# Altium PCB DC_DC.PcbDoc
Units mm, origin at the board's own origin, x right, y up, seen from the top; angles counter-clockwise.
Board outline 97.66 x 51.56 mm, 2 copper layers (Top Layer, Bottom Layer); 23 components, 9 nets, 55 pads, 2 vias.
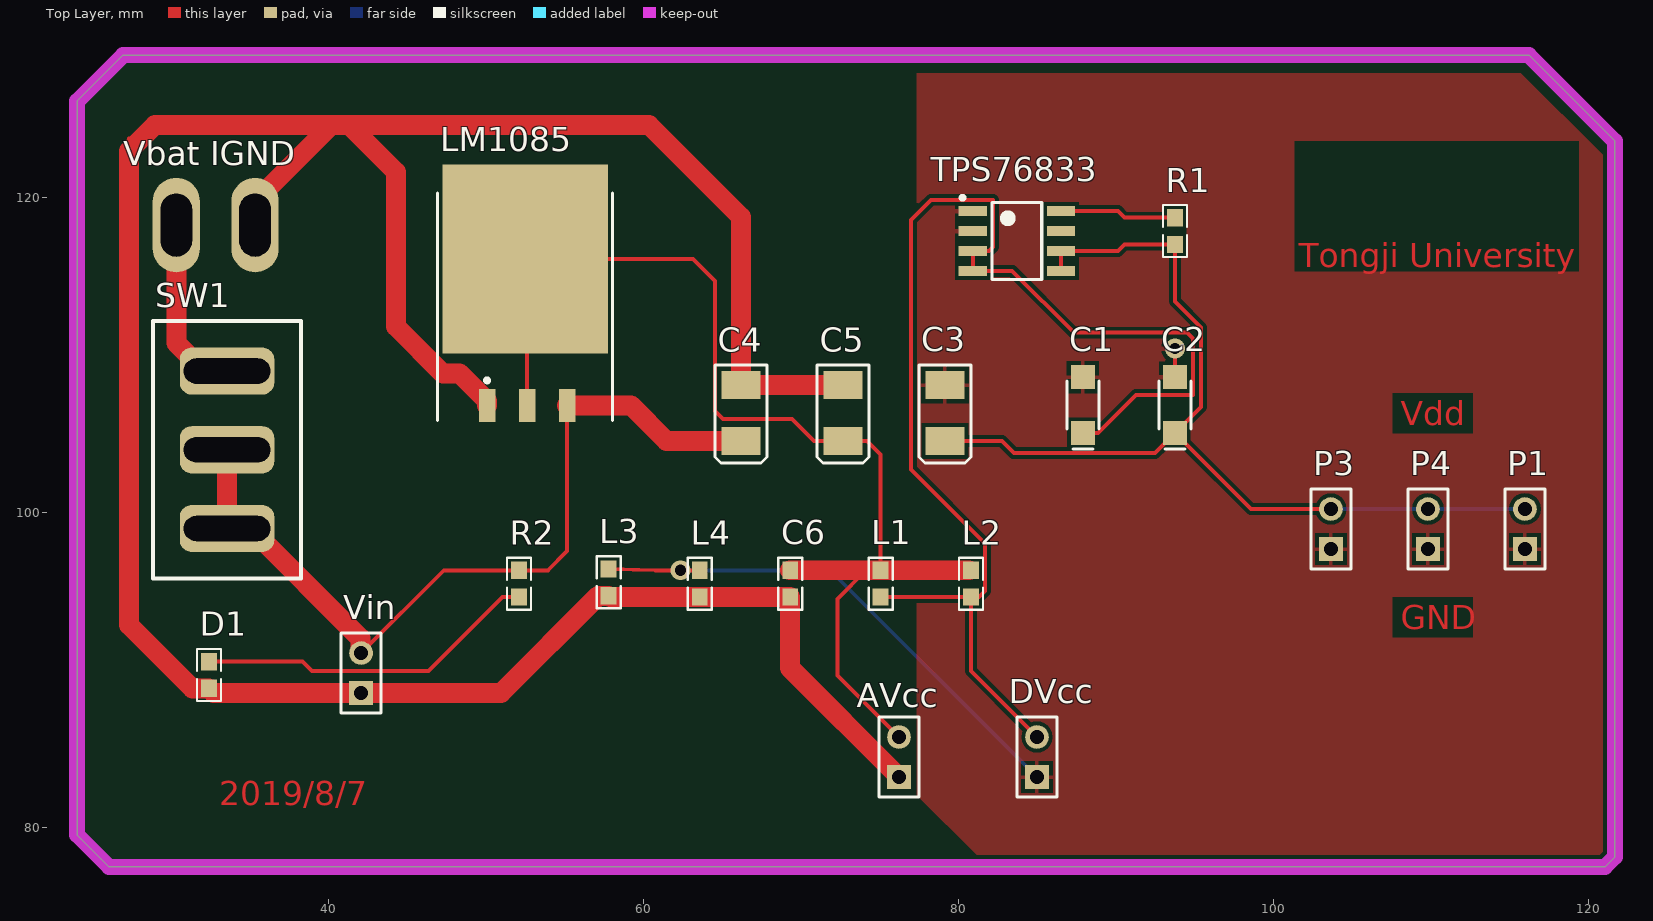
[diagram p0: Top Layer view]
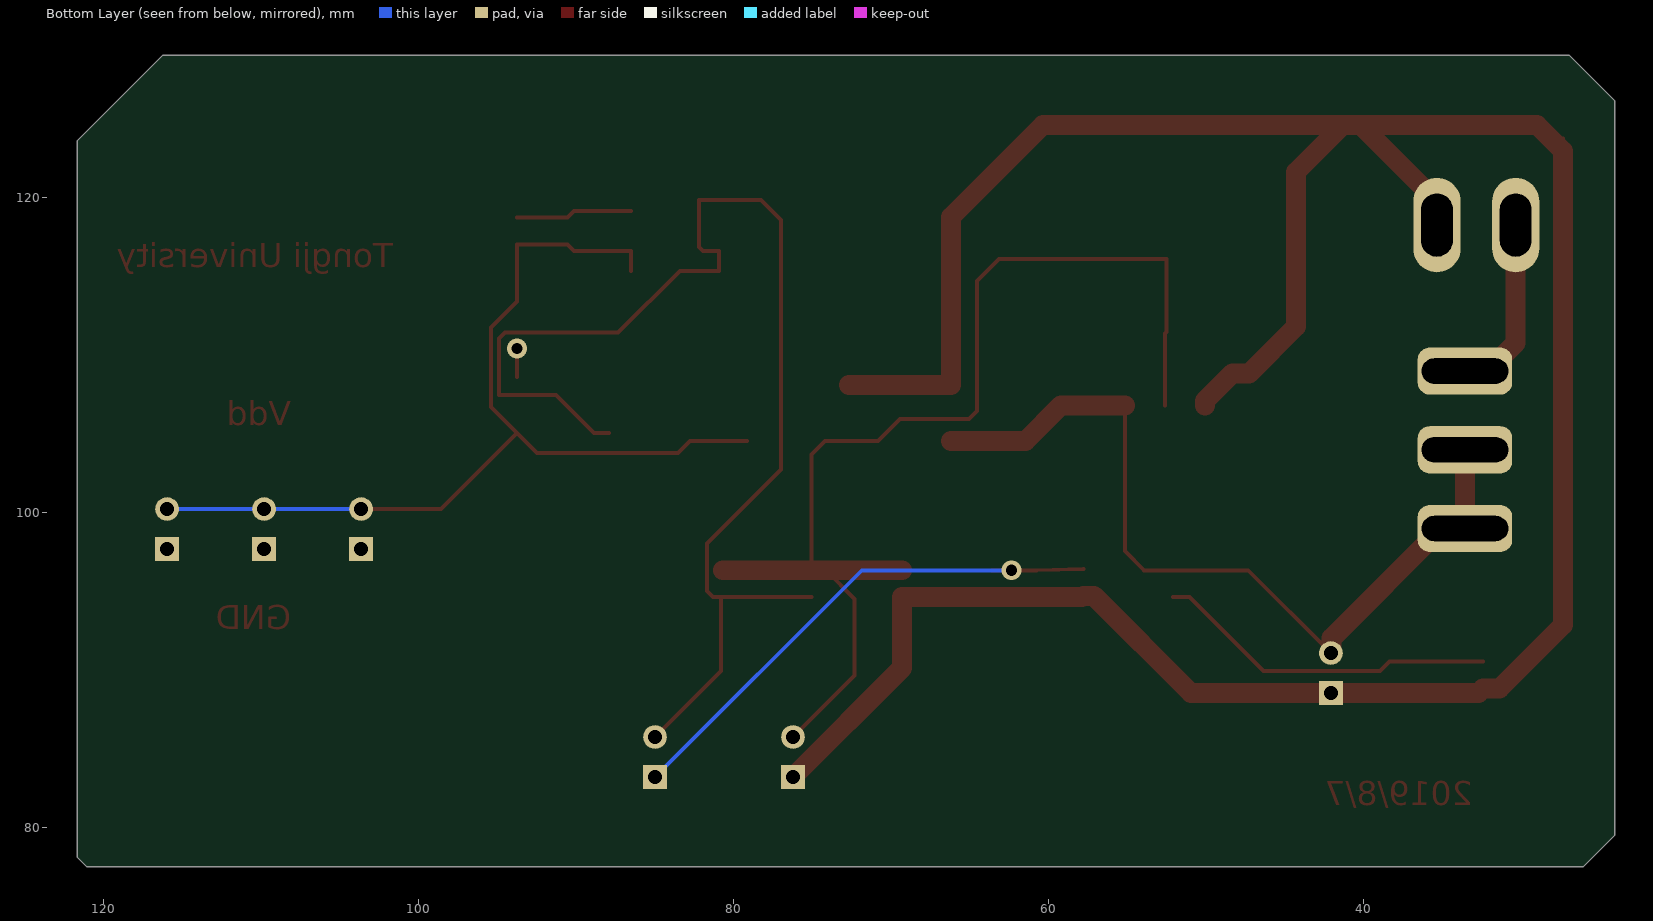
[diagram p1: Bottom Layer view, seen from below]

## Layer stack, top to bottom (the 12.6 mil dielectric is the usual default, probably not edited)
Top Solder: solder mask 0.0102, Solder Resist, Dk 3.5
Top Layer: signal copper 0.0356
Dielectric 1: dielectric 0.32, FR-4, Dk 4.8
Bottom Layer: signal copper 0.0356
Bottom Solder: solder mask 0.0102, Solder Resist, Dk 3.5

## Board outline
26.035,77.47 24.003,79.502 24.003,126.111 26.924,129.032 116.205,129.032 121.666,123.571 121.666,78.105 121.031,77.47

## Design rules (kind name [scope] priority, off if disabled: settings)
Clearance [All] p1: gap=0.254 ignorepadtopadclearanceinfootprint=FALSE except(0: Arc-Hole Track-Hole SMDPad-Hole THPad-Hole Via-Hole Fill-Hole Poly-Hole Region-Hole Text-Hole)
PolygonConnect [All] p1: connectstyle=Relief reliefconductorwidth=0.254 reliefentries=4 polygonreliefangle="90 Angle" airgapwidth=0.254
RoutingVias [All] p1: holewidth=0.711 width=1.27 viastyle="Through Hole" minholewidth=0.711 minwidth=1.27 maxholewidth=0.711 maxwidth=1.27
SolderMaskExpansion [All] p1: expansion=0.102
Width [All] p1: maxlimit=2.54 minlimit=0.254 preferedwidth=0.254
30 further rules are at their usual default settings.

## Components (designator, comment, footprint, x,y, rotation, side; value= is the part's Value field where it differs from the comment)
AVcc "Analog" HDR1X2 76.2,83.185 r90 top (schematic designator P6)
C1 "10uF/16V" CAP-1206 87.884,106.805 r90 top value=10uF
C2 "0.1uF/16V" CAP-1206 93.726,106.805 r90 top value=0.1uF
C3 "CT-22uF/16V" CAP-3528 79.121,106.299 r90 top
C4 "CT-22uF/16V" CAP-3528 66.167,106.299 r90 top
C5 "CT-22uF/16V" CAP-3528 72.644,106.299 r90 top
C6 "C-0.1uF/16V" 0603-1 69.291,95.465 r90 top value=100nF
D1 "D-LED" 0603-1 32.385,89.662 r270 top
DVcc "Digital" HDR1X2 84.963,83.185 r90 top (schematic designator P5)
L1 "L-MB" 0603-1 75.032,95.465 r90 top
L2 "L-MB" 0603-1 80.772,95.465 r90 top
L3 "L-MB" 0603-1 57.76,95.543 r270 top
L4 "L-MB" 0603-1 63.551,95.465 r270 top
LM1085 "U-LM1085" TO263-3 52.578,110.998 r0 top (schematic designator U2)
P1 "Header 2" HDR1X2 115.951,97.663 r90 top
P3 "Header 2" HDR1X2 103.632,97.663 r90 top
P4 "Header 2" HDR1X2 109.791,97.663 r90 top
R1 "249k" 0603-1 93.726,117.856 r270 top value=1K
R2 "R-4.7K" 0603-1 52.07,95.465 r90 top value=4K7
SW1 "SW-POWER" SWITCH_A4 33.528,108.966 r270 top
TPS76833 "U-TPS76833QD" SOIC8 83.687,117.221 r0 top (schematic designator U1)
"Vbat IGND" "T-POWER" PWR_HDR 30.306,118.237 r90 top (schematic designator T1)
Vin "V in" HDR1X2 42.037,88.519 r90 top (schematic designator P7)

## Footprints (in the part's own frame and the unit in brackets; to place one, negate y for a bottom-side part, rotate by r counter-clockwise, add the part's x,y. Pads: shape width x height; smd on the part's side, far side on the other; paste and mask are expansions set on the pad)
0603-1 [mm] "0603带丝印"
  rect 1.1x1 smd: 1(-0.85,0) 2(0.85,0)
  silkscreen extent -1.65,-0.76 1.65,0.76, body extent -0.8,-0.4 0.8,0.4, height 0.3
CAP-1206 [mil] "钽电容"
  rect 60x60 smd: 1(-70,0) 2(70,0)
  silkscreen extent -110,-40 60,40, body extent -65,-35 65,35, height 39
CAP-3528 [mm] "钽电容"
  rect 1.8x2.5 smd: 1(-1.778,0) 2(1.778,0)
  silkscreen extent -3.17,-1.65 3.05,1.65, body extent -1.91,-1.4 1.91,1.4, height 1.1
HDR1X2 [mm] "Connector; Header; 2 Position"
  rect 1.5x1.5 hole 0.9: 1(0,0)
  round 1.5 hole 0.9: 2(2.54,0)
  silkscreen extent -1.27,-1.27 3.81,1.27
PWR_HDR [mm]
  oval 6x3 hole 2 slot 4 at 0 deg: 1(0,0) 2(0,-5)
SOIC8 [mm] "SOIC,1.27mm pitch;8 pin,3.90mm W X 4.88mm L X 1.73mm H body"
  rect 1.8x0.65 smd: 1(-2.8,1.905) 2(-2.8,0.635) 3(-2.8,-0.635) 4(-2.8,-1.905) 5(2.8,-1.905) 6(2.8,-0.635) 7(2.8,0.635) 8(2.8,1.905)
  silkscreen extent -3.57,-2.45 1.58,2.87, body extent -3.11,-2.45 3.11,2.45, height 1.75
SWITCH_A4 [mm]
  rrect50% 3x6 hole 1.6 slot 5.5 at 90 deg: 1(0,0) 2(5,0) 3(10,0)
  silkscreen extent -3.18,-4.7 13.17,4.7
TO263-3 [mm] "LM2940/LM1086"
  rect 1.05x2.1 smd: 1(-2.54,-4.225) 2(0,-4.225) 3(2.54,-4.225)
  rect 10.5x12 smd: 2(-0.104,5.08)
  silkscreen extent -5.68,-5.17 5.42,9.28, body extent -5.46,-4.7 5.21,9.27, height 1.6

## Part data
AVcc DVcc Vin: library part "Header 2", "Header, 2-Pin"
C1 C2: library part "Cap Pol2", "Polarized Capacitor (Axial)"
C3 C4 C5: library part Cap-Pol-A, "钽电容"
C6: library part Cap, "Capacitor"
D1: library part LED2, "Typical RED, GREEN, YELLOW, AMBER GaAs LED"
L1 L2 L3 L4 R2: library part Res2, "Resistor"
LM1085: library part LM1085
P1 P3 P4: "Header, 2-Pin"
R1: library part Res3, "Resistor"
SW1: library part 大三端电源开关
TPS76833: library part TPS76850
"Vbat IGND": library part PWR_HDR

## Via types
v1: diameter 1.27, hole 0.711, Top Layer to Bottom Layer, 2 vias

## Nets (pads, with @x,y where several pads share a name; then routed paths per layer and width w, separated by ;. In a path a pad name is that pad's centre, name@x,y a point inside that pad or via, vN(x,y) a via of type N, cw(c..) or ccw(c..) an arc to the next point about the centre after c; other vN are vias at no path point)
DC+3.3V: C2.1 C3.1 P1.2 P3.2 P4.2 R1.2 TPS76833.5 TPS76833.6 | length 61.7
  Top Layer w0.254: C3.1 82.728,104.521 83.49,103.759 92.458,103.759 C2.1 ; TPS76833.5 TPS76833.6 90.094,116.586 90.514,117.006 R1.2 93.726,113.386 95.377,111.735 95.377,106.678 C2.1 ; P3.2 98.55,100.203 C2.1
  Bottom Layer w0.254: P3.2 P4.2 P1.2
DC+5V: C1.1 DVcc.2 L1.1 L2.1 TPS76833.3 TPS76833.4 | length 81.6
  Top Layer w0.254: L1.1 L2.1 ; DVcc.2 80.772,89.916 L2.1 ; C1.1 88.849,105.027 91.262,107.44 94.869,107.44 94.869,111.023 94.488,111.404 87.3,111.404 83.388,115.316 TPS76833.4 TPS76833.3 81.915,116.586 82.169,116.84 82.169,119.837 78.232,119.837 76.962,118.567 76.962,102.718 81.661,98.019 81.661,94.996 81.28,94.615 L2.1
DC+5V_ANALOG: AVcc.2 C5.1 C6.2 L1.2 L2.2 LM1085.2 | length 74.6
  Top Layer w0.254: LM1085.2@52.578,106.773 52.578,111.354 52.474,111.458 52.474,116.078 63.119,116.078 64.516,114.681 64.516,106.426 65.024,105.918 69.418,105.918 70.815,104.521 C5.1 74.168,104.521 75.032,103.657 L1.2 74.115,96.315 72.288,94.488 72.288,89.637 AVcc.2 ; L2.2@80.645,96.315 L2.2
  Top Layer w1.27: C6.2 L1.2 L2.2@80.645,96.315
GND: C1.2 C2.2 C3.2 DVcc.1 L3.1 L4.1 P1.1 P3.1 P4.1 TPS76833.1 TPS76833.2 | length 35.7
  Top Layer w0.254: L3.1 60.733,96.315 v1(62.33,96.315) L4.1 ; C2.2 v1(93.726,110.388)
  Bottom Layer w0.254: v1(62.33,96.315) 71.833,96.315 DVcc.1
IGND: "Vbat IGND.2" AVcc.1 C4.2 C5.2 C6.1 D1.2 L3.2 L4.2 LM1085.1 Vin.1 | length 260.5
  Top Layer w0.254: 27.305,123.749 27.305,122.936 27.305,92.837 31.33,88.812 31.623,88.519 32.678,88.519 Vin.1 50.927,88.519 ; L3.2@58.166,94.615 L4.2 ; 60.325,124.587 66.167,118.745 C4.2
  Top Layer w1.27: D1.2 31.33,88.812 27.305,92.837 27.305,122.936 28.956,124.587 40.156,124.587 ; D1.2@32.678,88.519 Vin.1 50.927,88.519 57.101,94.693 L3.2 57.838,94.615 L4.2 C6.1 69.291,90.094 AVcc.1 ; 35.306,118.237 35.306,119.737 40.156,124.587 ; LM1085.1 50.038,107.078 48.304,108.812 47.233,108.812 44.254,111.791 44.254,121.608 41.275,124.587 ; C5.2 C4.2 66.167,118.745 60.325,124.587 41.275,124.587 ; 40.156,124.587 41.275,124.587
NetD1_1: D1.1 R2.1 | length 21.9
  Top Layer w0.254: D1.1 38.317,90.512 38.913,89.916 46.33,89.916 51.029,94.615 R2.1
NetR1_1: R1.1 TPS76833.8 | length 7.4
  Top Layer w0.254: TPS76833.8 90.094,119.126 90.514,118.706 R1.1
VBAT: "Vbat IGND.1" SW1.1 | length 11.4
  Top Layer w1.27: 30.306,118.237 30.306,110.75 32.09,108.966 SW1.1
VCC_RAW: C4.1 LM1085.3 R2.2 SW1.2 SW1.3 Vin.2 | length 54.3
  Top Layer w0.254: Vin.2 47.293,96.315 R2.2 53.897,96.315 55.118,97.536 LM1085.3
  Top Layer w1.27: SW1.2 SW1.3 35.028,98.966 41.993,92.001 41.993,91.103 Vin.2 ; LM1085.3 59.189,106.773 61.441,104.521 C4.1
pads on no net: TPS76833.7

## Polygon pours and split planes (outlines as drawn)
GND on Top Layer "GND_L01_P028" (solid, remove dead copper, pour order 28): 77.343,127.889 115.697,127.889 121.031,122.555 121.031,78.232 81.153,78.232 77.343,82.042
GND on Top Layer "GND_L01_P026" (solid, remove dead copper, pour order 26): 76.581,125.222
GND on Top Layer "GND_L01_P018" (solid, remove dead copper, pour order 18): 129.413,97.282
GND on Top Layer "GND_L01_P014" (solid, remove dead copper, pour order 14): 67.437,127
GND on Top Layer "GND_L01_P012" (solid, remove dead copper, pour order 12): 60.452,127.254
no net on Top Layer "NONET_L01_P002" (solid, remove dead copper, pour order 2): 27.051,126.365

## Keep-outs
Top Layer:
  the board outline again, w1.016

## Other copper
Top Layer:
  text "Tongji University" at 101.6,115.57 h1.52
  text "Vdd" at 108.077,105.537 h1.52
  text "GND" at 108.077,92.583 h1.52
  text "2019/8/7" at 33.02,81.407 h1.52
